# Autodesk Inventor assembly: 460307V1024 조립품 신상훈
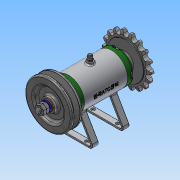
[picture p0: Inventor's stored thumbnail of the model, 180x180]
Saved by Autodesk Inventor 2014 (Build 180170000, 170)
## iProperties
Created: 2016-03
Part Number: 460307V1024 조립품 신상훈
Document SubType Name: Assembly
Designer: NET
Author: NET
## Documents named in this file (15)
- C:\Users\NET\Desktop\460307V1024 신상훈\460307V1024 조립품 신상훈.iam
- C:\Users\NET\Desktop\460307V1024 신상훈\본체1.ipt
- C:\Users\NET\Desktop\460307V1024 신상훈\커버.ipt
- C:\Users\NET\Desktop\460307V1024 신상훈\축.ipt
- C:\Users\NET\Desktop\460307V1024 신상훈\키 3 x 3 x 12.ipt
- C:\Users\NET\Desktop\460307V1024 신상훈\베어링 15 x 32 x 9.ipt
- C:\Users\NET\Desktop\460307V1024 신상훈\V벨트풀리.ipt
- C:\Users\NET\Desktop\460307V1024 신상훈\스프로킷.ipt
- C:\Users\NET\Desktop\460307V1024 신상훈\와셔 8x17.ipt
- C:\Users\NET\Desktop\460307V1024 신상훈\스프링와셔 8.ipt
- C:\Users\NET\Desktop\460307V1024 신상훈\너트 M 8.ipt
- C:\Users\NET\Desktop\460307V1024 신상훈\니플 M 6 x 0.75.ipt
- C:\Users\NET\Desktop\460307V1024 신상훈\와셔 6x11.5.ipt
- C:\Users\NET\Desktop\460307V1024 신상훈\볼트 M 6 x 8.ipt
- C:\Users\NET\Desktop\460307V1024 신상훈\볼트 M4 x 12.ipt
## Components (11 placed, 3 different names)
1. KS B 2023 6002 - 15 x 32 x 9:1
2. KS B 2023 6002 - 15 x 32 x 9:2
3. V벨트풀리:1 — 각도:2
4. ISO 4762 M4 x 12:2
5. ISO 4762 M4 x 12:3
6. ISO 4762 M4 x 12:4
7. ISO 4762 M4 x 12:5
8. ISO 4762 M4 x 12:1
9. ISO 4762 M4 x 12:6
10. ISO 4762 M4 x 12:7
11. ISO 4762 M4 x 12:8
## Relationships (1: Angle 1)
- 각도:2 [Angle]: V벨트풀리:1
